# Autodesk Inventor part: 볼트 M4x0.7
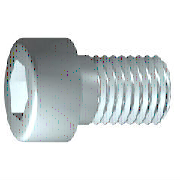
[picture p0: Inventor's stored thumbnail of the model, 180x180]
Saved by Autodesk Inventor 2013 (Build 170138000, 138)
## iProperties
IsCustomPart: 0
Created: 2012-02
Part Number: 볼트 M4x0.7
Material: 스테인리스강
Description: 6각 소켓 머리 캡 나사
Document SubType Name: Modeling
Standard: ISO 4762
Designer: mduedu
Standard Revision: Fourth edition 2004-03-01
Standards Organization: ISO
Language: ko-KR
Size Designation: M4 x 12
Categories: <MemberInstance><Categories><Category DisplayName="조임쇠" InternalName="e4da775c-781d-43d5-af7c-5136215cf5a6" Mnemonic="FSTN"><Category DisplayName="볼트" InternalN
Density: 7.75 g/cm^3
Author: mduedu
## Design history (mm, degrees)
sketch "스케치1"
  geometry: L1 (-1, 0)-(12, 0); L2 (12, 0)-(12, 2); L3 (12, 2)-(1.75, 2); L4 (1.75, 2)-(1.32, 2); L5 (1.32, 2)-(0, 2); L6 (0, 2)-(0, 3.5); L7 (0, 3.5)-(-4, 3.5); L8 (-4, 3.5)-(-4, 1.732); L9 (-4, 1.732)-(-2, 1.732); L10 (-2, 1.732)-(-1, 0); L11 (-7.2, 0)-(15.2, 0) reference; L12 (0, -0.7)-(0, 4.2) reference; L13 (1.75, 2)-(0, 2)
  constraints: 22 end point, 6 parallel, 2 collinear, 2 perpendicular, 1 horizontal, 1 point on line
  dimensions: "d1" = 10.25 distance from line of L3.end L2 (= GEL); "d2" = 0.42952 distance of L4.end L3.end (computed from GAL); "d3" = 4 distance between parallel lines of L8 L6 (= KOH); "d4" = 2 distance of L8.end L9.end (= INTI); "d5" = 60 deg angle of L10 L1; "d6" = 4 diameter of L3 L1 (= GD); "d7" = 4 diameter of L5 L1 (= BDM); "d8" = 3.4641 diameter of L9 L1 (= 1.1547 x SW); "d9" = 7 diameter of L7 L1 (= KOD); "d26" = 12 distance between parallel lines of L12 L2 (= NLG)
revolve "본체" sketch "스케치1" stored, may be unused: angle "d10" = 90 deg
sketch "스케치2"
  geometry: L1 (0, -4.9)-(0, 4.9) reference; L2 (-4.9, 0)-(4.9, 0) reference; L3 (1.732, 0)-(0.866, -1.5); L4 (0.866, -1.5)-(-0.866, -1.5); L5 (-0.866, -1.5)-(-1.732, 0); L6 (-1.732, 0)-(-0.866, 1.5); L7 (-0.866, 1.5)-(0.866, 1.5); L8 (0.866, 1.5)-(1.732, 0); 2 further points
  constraints: 12 end point, 1 coincident, 1 horizontal alignment, 1 point on line, 12 other
extrude "슬롯" join sketch "스케치2" stored distance "d11" = 10; taper "d12" = 0 deg
workplane "Work Plane1"
fillet "Fillet2" dims "d30" = 0.1 (= R)
body "Solid1"
fillet "모깎기1" dims "d17" = 0.4 (= RR)
feature "스레드" dims "d13" = 10.25 (= GEL), "d14" = 0
chamfer "모따기1" distance "d15" = 0.42941 (= -0.5 x SPD + 0.5 x GD); stored, may be unused: second distance "d16" = 0.42941 (= GUL), angle "d27" = 45 deg
other parameters: "GD" = 4 [user parameter; used in 2 equation terms], "NLG" = 12 [user parameter; used in 1 equation term], "GEL" = 10.25 [user parameter; used in 2 equation terms], "KOD" = 7 [user parameter; used in 1 equation term], "KOH" = 4 [user parameter; used in 1 equation term], "INTI" = 2 [user parameter; used in 1 equation term], "GAL" = 0.42941 (= 0.61345 x PTC) [user parameter; used in 1 equation term], "GUL" = 0.42941 (= 0.61345 x PTC) [user parameter; used in 1 equation term], "BDM" = 4 (= NND) [user parameter; used in 1 equation term], "SW" = 3 [user parameter; used in 2 equation terms], "RR" = 0.4 [user parameter; used in 1 equation term], "SPD" = 3.14117 (= NND - 1.2269 x PTC) [user parameter; used in 1 equation term], "d19" = 0, "d28" = 0, "d29" = 0, "R" = 0.1 [user parameter; used in 1 equation term], "TOA" = 30 deg [user parameter], "GD1" = 3.14117 (= THREADDIA - 1.2269 x PTC) [user parameter], "THREADDIA" = 4 [user parameter; used in 1 equation term], "FAWI" = 45 deg [user parameter], "TPU" = 14.28571 (computed from PTC) [user parameter], "PTC" = 0.7 [user parameter; used in 5 equation terms], "NND" = 4 [user parameter; used in 2 equation terms], "E0" = 3.465 (= 1.155 x SW) [user parameter]
